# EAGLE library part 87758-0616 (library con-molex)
6 Pin - 2mm Dual Row Single Wafer, Vertical T/H HDR Source: http://www.molex.com/pdm_docs/sd/877580616_sd.pdf
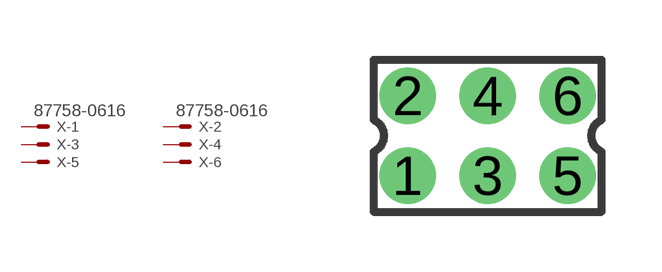
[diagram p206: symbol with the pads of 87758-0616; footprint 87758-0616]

Designator prefix X; gates -1=MV -2=MV -3=M -4=M -5=M -6=M

## 87758-0616 (MPN: 87758-0616; OC_FARNELL: 7472323; OC_NEWARK: 25M5667)  [87758-0616]
1  -1:S  pas
2  -2:S  pas
3  -3:S  pas
4  -4:S  pas
5  -5:S  pas
6  -6:S  pas

## Footprint 87758-0616 (pad centres in mm)
6 Pin - 2mm Dual Row Single Wafer, Vertical T/H HDR Source: http://www.molex.com/pdm_docs/sd/877580616_sd.pdf
drill 0.9 pad 1.27 round: 1 -2,-1; 2 -2,1; 3 0,-1; 4 0,1; 5 2,-1; 6 2,1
